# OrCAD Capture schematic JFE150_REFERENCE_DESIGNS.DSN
size A; title: Discrete JFET front-end, ultra-low noise piezoelectric; rev: 1.0; note: Datasheet: SLPS732
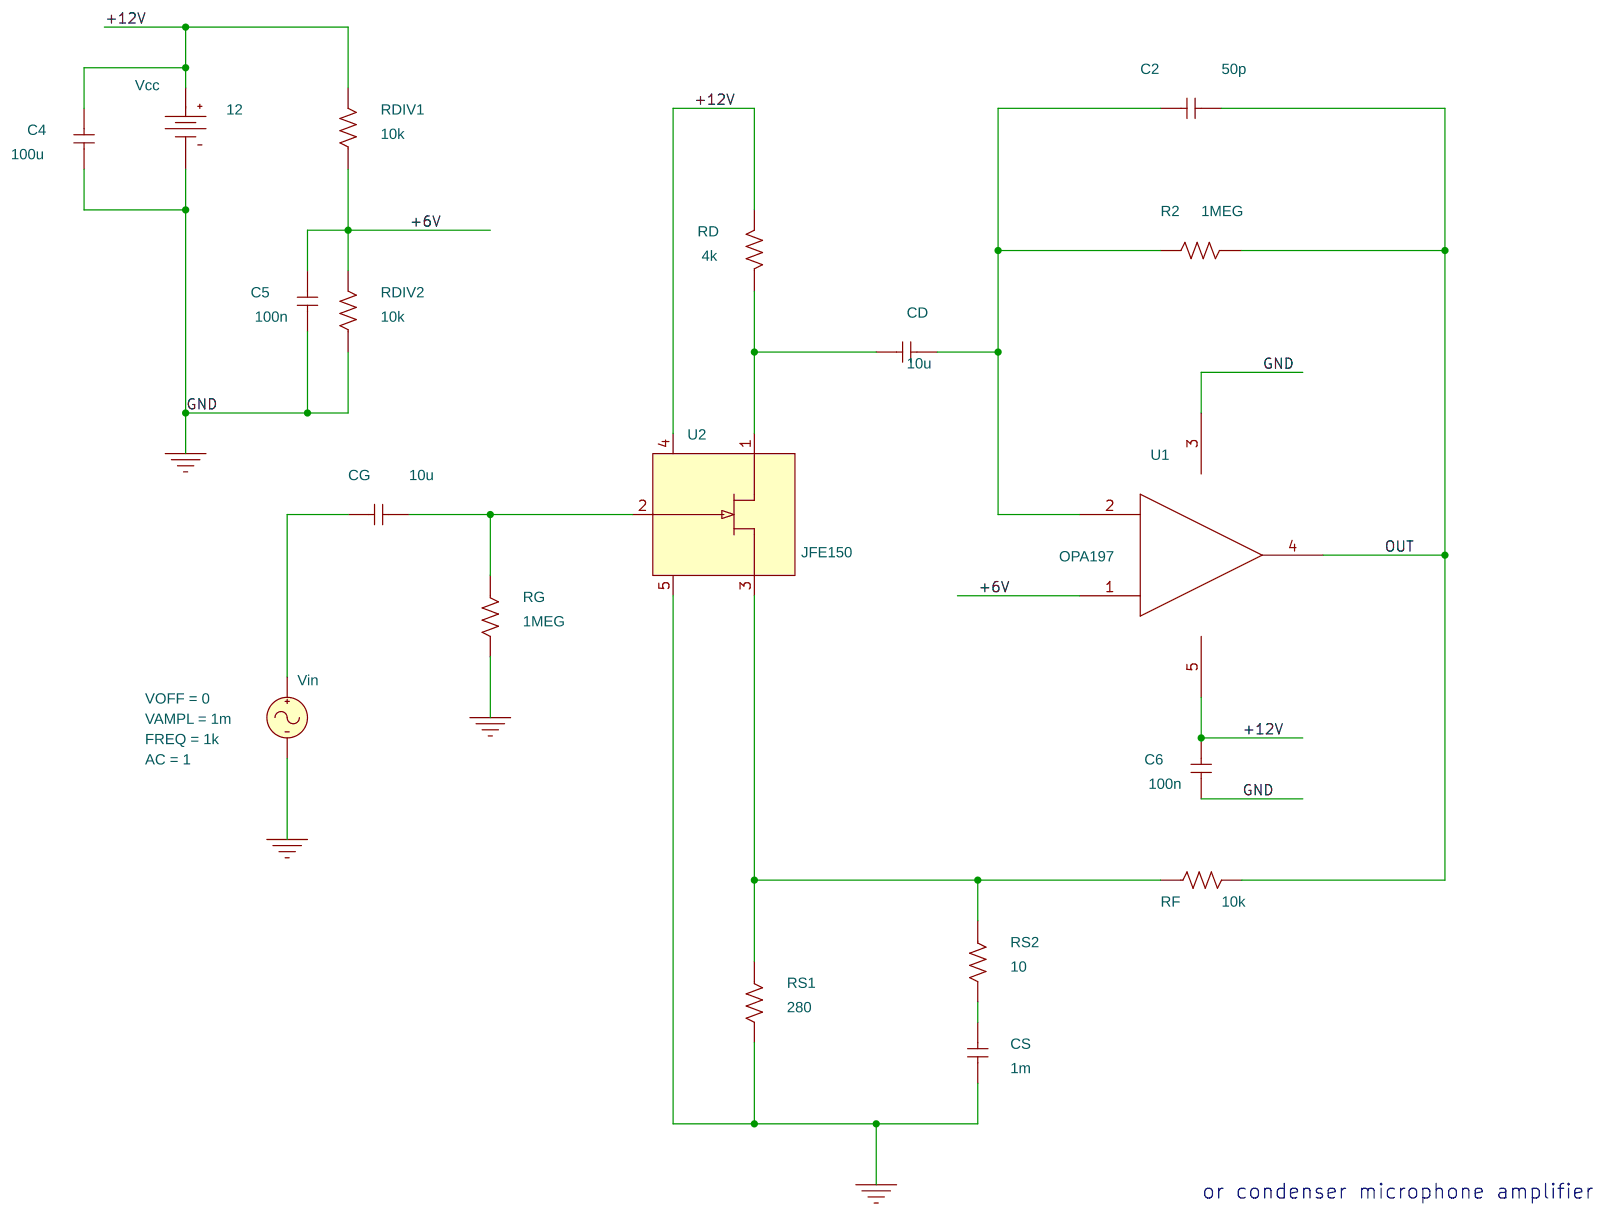
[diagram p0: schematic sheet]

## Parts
C2  50p  [cap196]
C4  100u  [cap196]
C5  100n  [cap196]
C6  100n  [cap196]
CD  10u  [cap196]
CG  10u  [cap196]
CS  1m  [cap196]
R2  1MEG  [AXRC05]
RD  4k  [AXRC05]
RDIV1  10k  [AXRC05]
RDIV2  10k  [AXRC05]
RF  10k  [AXRC05]
RG  1MEG  [AXRC05]
RS1  280  [AXRC05]
RS2  10  [AXRC05]
U1  OPA197
U2  JFE150
Vcc  VDC
Vin  VSIN

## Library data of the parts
C2 C4-C6 CD CG CS = C
R2 RD RDIV1 RDIV2 RF RG RS1 RS2 = R
U1 = OPA197
U2 = JFE150
Vcc = VDCR: AppProp: DC$Voltage$1$-1; DC: 12
Vin = VSIN: AC: 1; AppProp: Sine$Voltage$0$-1; DC: 0; FREQ: 1k; VAMPL: 1m; VOFF: 0

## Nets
+6V: C5.2 RDIV1.1 RDIV2.2 U1.1(IN+)
+12V: C4.2 C6.2 RD.2 RDIV1.2 U1.5(VCC) U2.4(VCC) Vcc.0(+)
0: C4.1 C5.1 C6.1 CS.1 RDIV2.1 RG.2 RS1.2 U1.3(VEE) U2.5(VEE) Vcc.1(-) Vin.2(-)
OUT: C2.2 R2.1 RF.2 U1.4(OUT)
N00301: C2.1 CD.2 R2.2 U1.2(IN-)
N00398: CD.1 RD.1 U2.1(D)
N00419: RF.1 RS1.1 RS2.1 U2.3(S)
N00426: CS.2 RS2.2
N00507: CG.2 RG.1 U2.2(G)
N00831: CG.1 Vin.1(+)

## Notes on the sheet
- or condenser microphone amplifier
